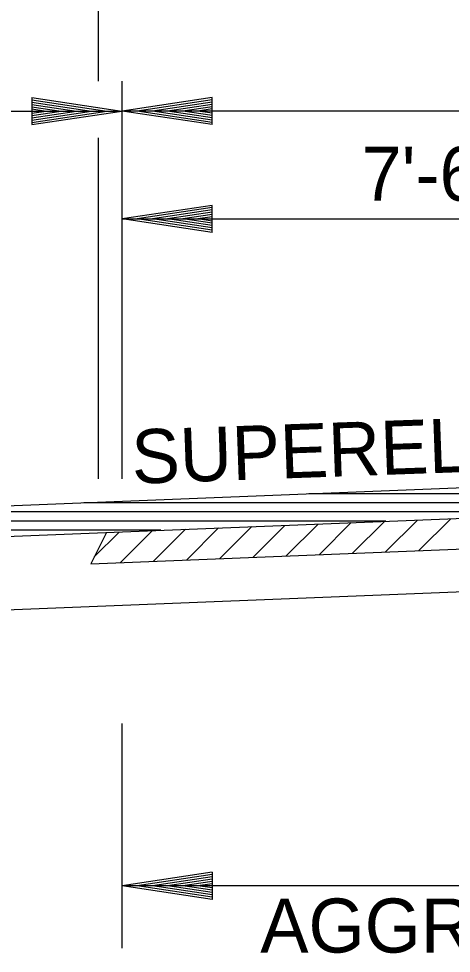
# Model space of a CAD drawing. Extents: x 1955768 to 1955917, y 566446 to 566546.
# Drawn here: x 1955831.02 to 1955835.83, y 566460.98 to 566471.36 of the extents above; entities that cross this region are included whole.
import ezdxf

# ---------------------------------------------------------------- set-up
doc = ezdxf.new("R2010")
doc.units = 0
doc.layers.add('R_Border', color=7, linetype='Continuous')
doc.layers.add('R_Grid', color=7, linetype='Continuous')

msp = doc.modelspace()

# ---------------------------------------------------------------- linework, layer by layer
at = {"layer": 'R_Border'}
for p, q in [((1955826.173, 566465.764), (1955847.173, 566466.604)), ((1955826.087, 566465.42), (1955847.339, 566466.271)), ((1955831.826, 566465.309), (1955847.506, 566465.937)), ((1955831.999, 566465.657), (1955831.826, 566465.309)), ((1955820.673, 566464.389), (1955847.173, 566465.449))]:
    msp.add_line(p, q, dxfattribs=at)
at = {"layer": 'R_Grid'}
for p, q in [((1955831.912, 566470.669), (1955831.912, 566477.299)), ((1955832.173, 566466.254), (1955832.173, 566470.669)), ((1955831.171, 566470.486), (1955832.171, 566470.336)), ((1955831.171, 566470.486), (1955831.171, 566470.186)), ((1955831.171, 566470.461), (1955832.004, 566470.336)), ((1955831.171, 566470.436), (1955831.832, 566470.336)), ((1955833.173, 566470.486), (1955832.173, 566470.336)), ((1955833.173, 566470.461), (1955832.34, 566470.336)), ((1955833.173, 566470.436), (1955832.512, 566470.336)), ((1955833.173, 566470.186), (1955833.173, 566470.486)), ((1955826.173, 566470.336), (1955832.173, 566470.336)), ((1955831.171, 566470.411), (1955831.666, 566470.336)), ((1955831.171, 566470.385), (1955831.496, 566470.336)), ((1955831.171, 566470.36), (1955831.329, 566470.336)), ((1955831.171, 566470.186), (1955832.171, 566470.336)), ((1955831.171, 566470.287), (1955831.496, 566470.336)), ((1955831.171, 566470.237), (1955831.832, 566470.336)), ((1955831.171, 566470.211), (1955832.004, 566470.336)), ((1955831.171, 566470.262), (1955831.666, 566470.336)), ((1955831.171, 566470.313), (1955831.329, 566470.336)), ((1955833.173, 566470.186), (1955832.173, 566470.336)), ((1955847.173, 566470.336), (1955832.173, 566470.336)), ((1955833.173, 566470.211), (1955832.34, 566470.336)), ((1955833.173, 566470.237), (1955832.512, 566470.336)), ((1955833.173, 566470.411), (1955832.678, 566470.336)), ((1955833.173, 566470.262), (1955832.678, 566470.336)), ((1955833.173, 566470.385), (1955832.848, 566470.336)), ((1955833.173, 566470.288), (1955832.848, 566470.336)), ((1955833.173, 566470.36), (1955833.015, 566470.336)), ((1955833.173, 566470.313), (1955833.015, 566470.336)), ((1955831.912, 566466.254), (1955831.912, 566470.039)), ((1955833.173, 566469.289), (1955832.173, 566469.139)), ((1955833.173, 566468.989), (1955833.173, 566469.289)), ((1955833.173, 566469.264), (1955832.34, 566469.139)), ((1955833.173, 566469.238), (1955832.512, 566469.139)), ((1955833.173, 566469.213), (1955832.678, 566469.139)), ((1955833.173, 566469.188), (1955832.848, 566469.139)), ((1955832.173, 566469.139), (1955839.673, 566469.139)), ((1955833.173, 566468.989), (1955832.173, 566469.139)), ((1955833.173, 566469.014), (1955832.34, 566469.139)), ((1955833.173, 566469.039), (1955832.512, 566469.139)), ((1955833.173, 566469.064), (1955832.678, 566469.139)), ((1955833.173, 566469.09), (1955832.848, 566469.139)), ((1955833.173, 566469.162), (1955833.015, 566469.139)), ((1955833.173, 566469.115), (1955833.015, 566469.139)), ((1955842.754, 566466.087), (1955834.247, 566466.087)), ((1955840.254, 566465.987), (1955831.747, 566465.987)), ((1955837.754, 566465.887), (1955829.247, 566465.887)), ((1955835.105, 566465.781), (1955826.673, 566465.781)), ((1955834.719, 566465.766), (1955834.365, 566465.411)), ((1955835.087, 566465.78), (1955834.733, 566465.426)), ((1955835.456, 566465.795), (1955835.101, 566465.441)), ((1955835.824, 566465.81), (1955835.47, 566465.456)), ((1955832.605, 566465.681), (1955826.152, 566465.681)), ((1955832.141, 566465.662), (1955831.863, 566465.385)), ((1955832.509, 566465.677), (1955832.155, 566465.323)), ((1955832.878, 566465.692), (1955832.523, 566465.338)), ((1955833.246, 566465.707), (1955832.892, 566465.353)), ((1955833.614, 566465.722), (1955833.26, 566465.367)), ((1955833.982, 566465.736), (1955833.628, 566465.382)), ((1955834.351, 566465.751), (1955833.996, 566465.397)), ((1955832.173, 566461.039), (1955832.173, 566463.534)), ((1955833.173, 566461.883), (1955832.173, 566461.733)), ((1955833.173, 566461.858), (1955832.34, 566461.733)), ((1955833.173, 566461.833), (1955832.512, 566461.733)), ((1955833.173, 566461.883), (1955833.173, 566461.583)), ((1955847.173, 566461.733), (1955832.173, 566461.733)), ((1955833.173, 566461.583), (1955832.173, 566461.733)), ((1955833.173, 566461.608), (1955832.34, 566461.733)), ((1955833.173, 566461.634), (1955832.512, 566461.733)), ((1955833.173, 566461.808), (1955832.678, 566461.733)), ((1955833.173, 566461.659), (1955832.678, 566461.733)), ((1955833.173, 566461.782), (1955832.848, 566461.733)), ((1955833.173, 566461.684), (1955832.848, 566461.733)), ((1955833.173, 566461.757), (1955833.015, 566461.733)), ((1955833.173, 566461.71), (1955833.015, 566461.733))]:
    msp.add_line(p, q, dxfattribs=at)

# ---------------------------------------------------------------- texts
at = {"layer": 'R_Border'}
for s, p in [('7\'-6"', (1955834.834, 566469.34)), ('AGGREGATE BASE COURSE', (1955833.709, 566460.992))]:
    msp.add_text(s, height=0.6, dxfattribs=at).set_placement(p)
msp.add_text('SUPERELEVATION', height=0.6, rotation=2.0327, dxfattribs=at).set_placement((1955832.289, 566466.197))

doc.saveas('drawing.dxf')
